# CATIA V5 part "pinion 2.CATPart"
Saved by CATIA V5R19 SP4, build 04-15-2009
Part number: pinion 2
Bounding box of the stored display mesh (mm): x 0 to 22.15, y -45.349 to 45.349, z -45.156 to 45.156
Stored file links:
  G:\EU_thinkMotion\CFAO_2010\MMS_groupe1\MMS_groupe1\A reprendre\OK\rdeneffle\pinion 2.CATPart
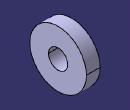
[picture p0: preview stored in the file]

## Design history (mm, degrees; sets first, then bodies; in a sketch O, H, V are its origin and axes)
Parameters
  `rayon interieur` = 15.505 mm
  `rayon extérieur` = 45.349 mm
Body1 (main body)
  Sketch1 on yz-plane, origin (0, 0, 0), H (0, 1, 0), V (0, 0, 1)
    circle A1 centre (0, 0) radius 15.505
    circle A2 centre (0, 0) radius 45.349
    radius A2 = 45.349 {= `rayon extérieur`}
    radius A1 = 15.505 {= `rayon interieur`}
  Pad1: profile Sketch1, direction (1, 0, 0), length 22.15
